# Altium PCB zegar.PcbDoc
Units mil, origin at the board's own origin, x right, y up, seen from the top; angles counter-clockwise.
Board outline 6000 x 4000 mil, 2 copper layers (Top Layer, Bottom Layer); 33 components, 30 nets, 135 pads, 16 vias.
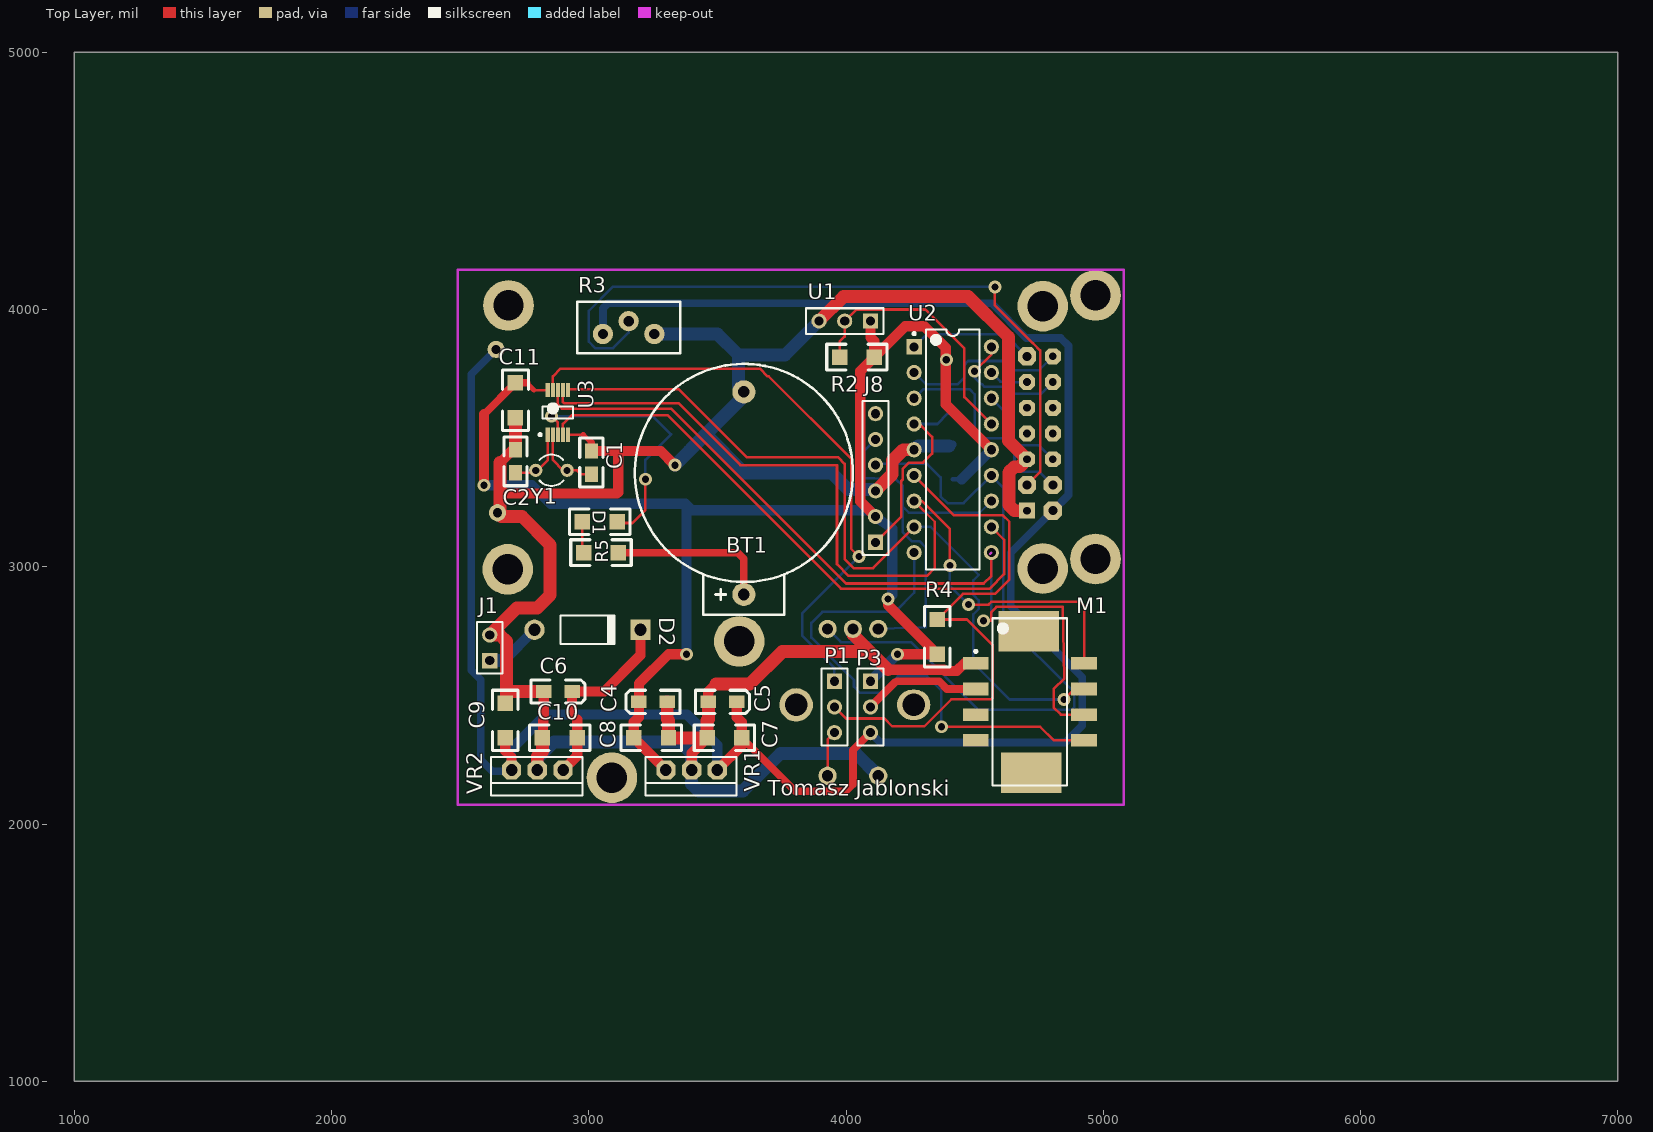
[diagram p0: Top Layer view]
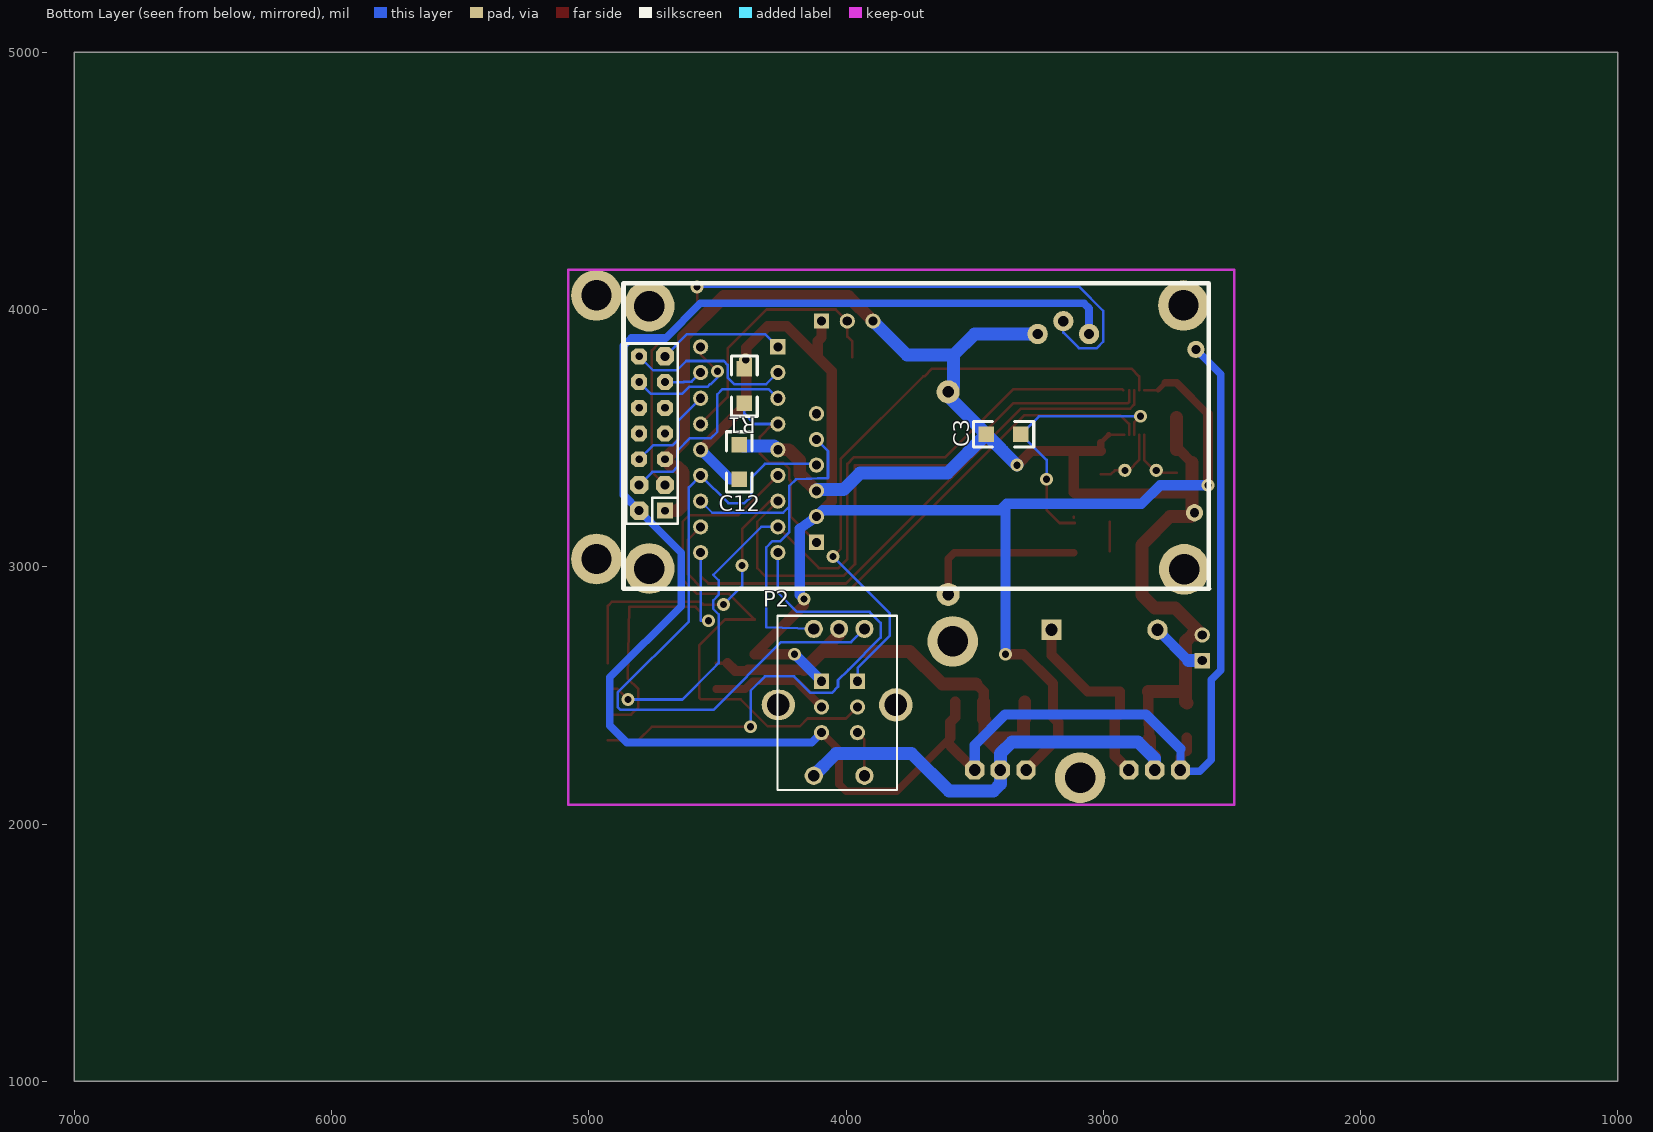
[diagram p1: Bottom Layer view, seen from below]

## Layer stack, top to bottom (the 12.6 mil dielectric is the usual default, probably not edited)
Top Layer: signal copper 1.4
Dielectric: dielectric 12.6, FR-4, Dk 4.8
Bottom Layer: signal copper 1.4

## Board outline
1000,1000 7000,1000 7000,5000 1000,5000

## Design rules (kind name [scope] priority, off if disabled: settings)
Clearance [All] p1: gap=10
PolygonConnect [All] p1: connectstyle=Relief reliefconductorwidth=10 reliefentries=4 polygonreliefangle="90 Angle"
RoomDefinition zegar [InComponentClass('zegar')] p1: confinementstyle=ConfineIn formatcopy=TRUE lockcomponents=FALSE outline 0,0 2000,0 2000,1000 0,1000
RoutingVias [All] p1: holewidth=28 width=50 viastyle="Through Hole" minholewidth=28 minwidth=50 maxholewidth=28 maxwidth=50
SMDNeckDown SMD+3,3 [InNet('+3,3V')] p1: percent=50.000
SMDNeckDown SMD_gnd [InNet('GND')] p2: percent=50.000
SilkscreenOverComponentPads [All] p1: minsilkscreentomaskgap=10
SolderMaskExpansion [All] p1: expansion=4
Width +5V [InNet('+5V')] p1: maxlimit=30 minlimit=10 preferedwidth=30
Width +3,3V [InNet('+3,3V')] p2: maxlimit=40 minlimit=10 preferedwidth=40
Width GND [InNet('GND')] p3: maxlimit=50 minlimit=40 preferedwidth=50
27 further rules are at their usual default settings.

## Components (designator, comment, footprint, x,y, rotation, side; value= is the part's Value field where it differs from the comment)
BT1 "Battery" BAT -3405,-4155 r270 top
C1 "22p" 0805 3010,3450 r270 top
C2 "22p" 0805 2715,3455 r270 top
C3 "100n" 1206 3455,3515 r180 bottom
C4 "Cap Pol2" 3216 3195,2475 r180 top
C5 "" 3216 3575,2475 r0 top
C6 "" 3216 2935,2515 r0 top
C7 "Cap" 1206 3595,2335 r180 top
C8 "Cap" 1206 3175,2335 r0 top
C9 "Cap" 1206 2675,2335 r90 top
C10 "Cap" 1206 2955,2335 r180 top
C11 "100n" 1206 2715,3715 r270 top
C12 "100n" 1206 4415,3475 r270 bottom
D1 "Diode" 1206 2975,3175 r0 top
D2 "1N4007" DIO10.46-5.3x2.8 2995,2755 r0 top
J1 "PWR" HDR1X2 2615,2635 r90 top
J8 "ICSP" HDR1X6 4115,3095 r90 top
M1 "TR52B" TR52B 4715,2475 r0 top
P1 "imp_sel" HDR1X3 3955,2555 r270 top
P2 "imp" IMP_PIHER 4015,2475 r0 bottom
P3 "TR52_PW" HDR1X3 4095,2555 r270 top
R1 "1k" 1206 4395,3635 r90 bottom
R2 "1k" 1206 3975,3815 r0 top
R3 "" PR 3155,3955 r180 top
R4 "1k" 1206 4355,2795 r270 top
R5 "1K" 1206 3115,3055 r180 top
U1 "DS18B20" HDR1X3 4095,3955 r180 top
U2 "PIC16F88" DIP-18 4415,3455 r0 top
U3 "MCP79512" MCP79512 2880,3600 r90 top
VR1 "Volt Reg" 78XXST 3475,2195 r180 top
VR2 "Volt Reg" 78XXST 2875,2195 r180 top
Y1 "XTAL" BCY-W2/D3.1 2855,3375 r270 top
? "LCD" lcd1x6 3735,3695 r180 bottom

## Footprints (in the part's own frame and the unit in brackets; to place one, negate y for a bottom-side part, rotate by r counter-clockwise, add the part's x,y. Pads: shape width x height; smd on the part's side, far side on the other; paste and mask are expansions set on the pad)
78XXST [mil]
  oct 75x75 hole 45: 1(-25,-15) 2(75,-15) 3(175,-15)
  silkscreen extent -100,-65 255,85
0805 [mil]
  rect 60x50 smd: 1(0,0) 2(90,0)
  silkscreen extent -50,-45 140,45
1206 [mil]
  rect 60x60 smd: 1(0,0) 2(135,0)
  silkscreen extent -50,-50 185,50
3216 [mil]
  rect 60x50 smd: 1(0,0) 2(-110,0)
  silkscreen extent -160,-45 50,45
BAT [mil]
  round 90 hole 45: 1(-7047.24,7007.87) 2(-7834.65,7007.87)
  silkscreen extent -7944,6584 -6969,7432
BCY-W2/D3.1 [mm] "Crystal, Thru-Hole; 2 Leads; Body 3.1 x 8.2 mm (Dia.xH)"
  round 1.3 hole 0.7: 1(0,1.55) 2(0,-1.55)
  silkscreen extent -1.55,-1.19 1.55,1.17
DIO10.46-5.3x2.8 [mm] "Diode, Axial; Body 5.2 x 2.7 mm (LxDia. max), Lead Dia. 0.86 mm (max)"
  round 2 hole 1.2: 1(-5.23,0)
  rect 2x2 hole 1.2: 2(5.23,0)
  silkscreen extent -2.65,-1.4 2.75,1.4
DIP-18 [mm] "DIP; 18 Leads; Row Spacing 7.62 mm; Pitch 2.54 mm"
  rect 1.5x1.5 hole 0.9: 1(-3.81,10.16)
  round 1.5 hole 0.9: 2(-3.81,7.62) 3(-3.81,5.08) 4(-3.81,2.54) 5(-3.81,0) 6(-3.81,-2.54) 7(-3.81,-5.08) 8(-3.81,-7.62) 9(-3.81,-10.16) 10(3.81,-10.16) 11(3.81,-7.62) 12(3.81,-5.08) 13(3.81,-2.54) 14(3.81,0) 15(3.81,2.54) 16(3.81,5.08) 17(3.81,7.62) 18(3.81,10.16)
  silkscreen extent -3.93,-11.85 2.65,11.85, body extent -3.6,-11.8 3.6,11.8, height 5.08
HDR1X2 [mm] "Connector; Header; 2 Position"
  rect 1.5x1.5 hole 0.9: 1(0,0)
  round 1.5 hole 0.9: 2(2.54,0)
  silkscreen extent -1.27,-1.27 3.81,1.27
HDR1X3 [mm] "Connector; Header; 3 Position"
  rect 1.5x1.5 hole 0.9: 1(0,0)
  round 1.5 hole 0.9: 2(2.54,0) 3(5.08,0)
  silkscreen extent -1.27,-1.27 6.35,1.27
HDR1X6 [mm] "Connector; Header; 6 Position"
  rect 1.5x1.5 hole 0.9: 1(0,0)
  round 1.5 hole 0.9: 2(2.54,0) 3(5.08,0) 4(7.62,0) 5(10.16,0) 6(12.7,0)
  silkscreen extent -1.27,-1.27 13.97,1.27
IMP_PIHER [mm]
  round 1.8 hole 1.1: 1(-2.2,-7.2) 2(0.3,-7.2) 3(2.8,-7.2) 4(-2.2,7.3) 5(2.8,7.3)
  round 3.3 hole 2.2: 71(-5.3,0.3)
  oval 3.3x3 hole 2.2: 72(6.3,0.3)
  silkscreen extent -5.4,-8.5 6.4,8.7
lcd1x6 [mil]
  round 196.85 hole 118.11: 0(-1030,-702) 0(-1030,318) 0(1047,321) 0(1050,-705)
  rect 62x62 hole 30: 1(-969,-477)
  oct 70.87x70.87 hole 35.43: 2(-1069,-477) 3(-969,-377) 4(-1069,-377) 13(-969,123)
  oct 62x62 hole 30: 5(-969,-277) 6(-1069,-277) 7(-969,-177) 8(-1069,-177) 9(-969,-77) 10(-1069,-77) 11(-969,23) 12(-1069,23) 14(-1069,123)
  round 66.93 hole 35.43: 15(1095,150) 16(1090,-485)
  silkscreen extent -1130,-781 1146,407
MCP79512 [mm] "SSOP, 10-Leads, Body 3.0x3.0mm (max), Pitch 0.50mm, IPC Medium Density"
  rect 1.4x0.4 smd: 1(-2.2,1) 2(-2.2,0.5) 3(-2.2,0) 4(-2.2,-0.5) 5(-2.2,-1) 6(2.2,-1) 7(2.2,-0.5) 8(2.2,0) 9(2.2,0.5) 10(2.2,1)
  silkscreen extent -2.32,-1.5 0.7,1.87, body extent -1.5,-1.5 1.5,1.5, height 2.65
PR [mil]
  round 79 hole 40: 1(-100,50) 2(100,50) W(0,0)
  silkscreen extent -200,-75 200,125
TR52B [mm]
  rect 6x4 smd: 0(-0.127,6.985) 0(0.127,-6.985)
  rect 2.55x1.25 smd: 1(-5.35,-3.81) 2(-5.35,-1.27) 3(-5.35,1.27) 4(-5.35,3.81) 5(5.35,-3.81) 6(5.35,-1.27) 7(5.35,1.27) 8(5.35,3.81)
  silkscreen extent -5.47,-8.25 3.68,8.25

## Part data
BT1: "Multicell Battery"
C1 C2 C3 C11 C12: library part Cap, "Capacitor"
C4: "Polarized Capacitor (Axial)"
C5 C6: library part "Cap Pol2", "Polarized Capacitor (Axial)"
C7 C8 C9 C10: "Capacitor"
D1: "Default Diode"
D2: library part "Diode 1N4007", "1 Amp General Purpose Rectifier"
J1: library part "Header 2", "Header, 2-Pin"
J8: library part "Header 6", "Header, 6-Pin"
M1: library part "Header 4X2A", "Header, 4-Pin, Dual row"
P1 P3 U1: library part "Header 3", "Header, 3-Pin"
P2: library part "Header 5", "Header, 5-Pin"
R1 R2 R4 R5: library part res2, "Resistor"
R3: library part RPot, "Potentiometer"
U2: library part PIC16F62X
VR1 VR2: "Voltage Regulator"
Y1: "Crystal Oscillator"

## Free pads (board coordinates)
  round 196.85 hole 118.11: 3(3090,2180) 3(3585,2710) 3(4970,3030) 3(4970,4055)

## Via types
v1: diameter 50, hole 28, Top Layer to Bottom Layer, 16 vias

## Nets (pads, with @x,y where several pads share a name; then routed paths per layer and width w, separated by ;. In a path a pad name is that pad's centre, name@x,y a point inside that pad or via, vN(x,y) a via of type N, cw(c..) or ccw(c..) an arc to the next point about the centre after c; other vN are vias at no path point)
1-WIRE: R2.1 U1.2 U2.15 | length 1031.6
  Top Layer w10: R2.1 3975,3875 3995,3895 U1.2 4040,4000 4308.31,4000 4460,3848.31 4460,3660 U2.15
+3,3V: C4.1 C8.1 C11.1 C12.2 J8.2 P3.1 R1.2 R2.2 R4.2 U1.1 U2.14 U3.10 VR1.3 | length 6162.2
  Top Layer w10: 2786.61,3686.61 U3.10
  Top Layer w20: 2758.23,3715 2786.61,3686.61
  Top Layer w30: 2593,3593 C11.1 2758.23,3715
  Top Layer w40: v1(2593,3317) 2593,3593 ; VR1.3 3257,2253 C8.1 3175,2395 3195,2415 3195,2545 3310,2660 v1(3380,2660) ; U1.1 4095,3892 4110,3877 R2.2 ; J8.2 4055,3255 4055,3760 R2.2 ; v1(4163,2875) 4163,2852 R4.2 v1(4200,2660) ; U2.14 4388,3632 4388,3851 4304,3935 4230,3935 R2.2
  Bottom Layer w18: C12.2 4450,3340
  Bottom Layer w40: v1(2593,3317) 2779,3317 2851.2,3244.8 3375.2,3244.8 3400,3220 4090,3220 J8.2 4179.31,3148.69 4179.31,2891.31 v1(4163,2875) ; v1(3380,2660) 3380,3175 3380,3235 ; P3.1 v1(4200,2660) ; 4450,3340 U2.14
  other v1: 4390,3805
+5V: ?.2 ?.15 C5.1 C7.1 C9.1 P3.3 R3.2 VR1.1 VR2.3 | length 8616.3
  Top Layer w30: 2675,2285 2700,2260 ; C7.1@3595,2305 C7.1 3803,2127 3999,2127 4027,2155 4027,2287 P3.3
  Top Layer w40: 2675,2285 C9.1 ; VR2.3 2700,2260 ; VR1.1 C7.1@3595,2305 ; C5.1 3575,2415 3595,2395 C7.1
  Bottom Layer w30: ?.15 2543,3748 2543,2597.94 2580,2560.94 2580,2250 2625,2205 2695,2205 VR2.3 2700,2292.07 ; R3.2 3055,4004 3075,4024 4566,4024 4701,3889 4835,3889 4865,3859 4865,3279 ?.2 4641,3055 4641,2847 4918,2570 4918,2383 4852,2317 4133,2317 P3.3
  Bottom Layer w40: 2700,2292.07 2833.93,2426 3381.22,2426 3500,2307.22 VR1.1
ALM: P1.1 U3.9 | length 2391.4
  Top Layer w10: 2860,3740 2860.31,3740.31 ; U3.9 2860.31,3740.31 ; v1(4050,3040) 4020,3070 4020,3420 3699.69,3740.31 3694.69,3740.31 3665,3770 2890,3770 2860.31,3740.31
  Bottom Layer w10: P1.1 3955,2606.72 3830,2731.72 3830,2820 v1(4050,3040)
GND: ?.1 ?.5 ?.16 BT1.2 C1.1 C2.1 C3.1 C4.2 C5.2 C6.2 C7.2 C8.2 C9.2 C10.2 C11.2 C12.1 J1.2 J8.3 M1.4 P2.2 P2.5 R3.1 U1.3 U2.5 U3.5 VR1.2 VR2.2 | length 10769.3
  Top Layer w10: U3.5 2978.39,3513.39
  Top Layer w14.76: M1.4@4460.81,2625 M1.4
  Top Layer w20: 2978.39,3513.39 3010,3481.77
  Top Layer w25: C2.1@2705,3455 C2.1
  Top Layer w30: C1.1 3010,3481.77
  Top Layer w40: 2655,3285 3110,3285 3115,3290 3115,3450 ; 2655,3405 C2.1@2705,3455 ; C10.2 2825,2430 C6.2 ; C1.1 3115,3450 ; v1(3335,3395) 3280,3450 3115,3450 ; VR1.2 3400,2275 C7.2 ; C5.2 3465,2515 3494,2544 ; 4165,2600 4380.64,2600 4385.64,2595 4430.81,2595 M1.4@4460.81,2625
  Top Layer w50: ?.16@2655,3215 2655,3285 2655,3405 ; ?.16@2660,3195 2740,3195 2850,3085 2850,2890 2800,2840 2720,2840 J1.2 2655,2735 2679.53,2710.47 2679.53,2515 ; C9.2 2679.53,2474.53 2679.53,2515 ; C2.1 C11.2 ; VR2.2 2800,2262 2820,2282 C10.2 ; C6.2 2679.53,2515 ; C4.2 3305,2407 3310,2402 C8.2 C7.2 3460,2402 3465,2407 C5.2 ; 3494,2544 3626,2544 3752,2670 4091.2,2670 ; U1.3 3990,4050 4475,4050 4632,3893 4632,3490 ?.5 4675,3389 4655,3389 4633,3367 4633,3240 4655,3218 ?.1 ; P2.2 4026.81,2736.19 4163,2600 ; J8.3 4180,3360 4180,3412.5 4222.5,3455 U2.5
  Bottom Layer w30: 4330,3475 C12.1
  Bottom Layer w50: VR2.2 2800,2254.5 2864.5,2319 3355,2319 3400,2274 VR1.2 3400,2155 3427,2128 3599,2128 3745,2274 4038.83,2274 P2.5 ; R3.1 3499.88,3905 3582.13,3822.76 ; v1(3335,3395) C3.1 ; 3390,3450 C3.1 ; U1.3 3762.76,3822.76 3582.13,3822.76 ; J8.3 4110.2,3299.8 4010.2,3299.8 3945,3365 3605,3365 C3.1 ; U2.5 4280,3470 C12.1@4400,3470 ; C3.1 3602.87,3662.87 BT1.2 3582.13,3700.39 3582.13,3822.76
INT: P1.2 R4.1 U2.6 | length 2166.2
  Top Layer w10: P1.2 4000,2410 4149,2410 4179,2380 4305,2380 4410,2485 4565,2485 4570,2490 4570,2695 4470,2795 R4.1 4454.55,2894.55 4578.55,2894.55 4635,2951 4635,3175 4610,3200 4420,3200 U2.6
LCD_D0: ?.11 U2.17 | length 154.3
  Bottom Layer w10: U2.17 4600.47,3719.53 4629.53,3719.53 4631.06,3718 ?.11
LCD_D1: ?.12 U2.18 | length 495.8
  Top Layer w10: v1(4500,3760) 4565,3825 U2.18
  Bottom Layer w10: v1(4500,3760) 4500,3735.53 4525.53,3710 4528.76,3710 4539.23,3699.53 4610,3699.53 4637.53,3672 4758,3672 ?.12
LCD_D2: ?.13 U2.1 | length 494.9
  Bottom Layer w10: U2.1 4314,3904 4618,3904 ?.13
LCD_D3: ?.14 U2.2 | length 661.5
  Bottom Layer w10: U2.2 4310,3710 4435,3710 4460,3735 4460,3785 4475,3800 4621,3800 4657,3764 4750,3764 ?.14
LCD_E: ?.6 U2.16 | length 379.9
  Bottom Layer w10: U2.16 4652,3568 4652,3495 4675,3472 4750,3472 ?.6
LCD_RS: ?.4 U2.3 | length 829.8
  Bottom Layer w10: U2.3 4300,3690 4480,3690 4480,3690.47 4500.47,3670 4500.47,3524.53 4525,3500 4606,3500 4655,3451 4655,3389 4675,3369 4753,3369 ?.4
Net_3: ?.3 | length 2837.6
  Top Layer w10: v1(4579,4088) 4579,4016 4726.57,3868.43 4727.93,3868.43 4755,3841.36 4755,3369 ?.3
  Bottom Layer w10: 3155,3955 3155,3910 3095,3850 3025,3850 3000,3875 3000,3995 3093,4088 v1(4579,4088)
NetBT1_1: BT1.1 R5.1 | length 636.7
  Top Layer w30: R5.1 3579.11,3055 3602.87,3031.24 BT1.1
NetC1_2: C1.2 U3.2 Y1.1 | length 270.7
  Top Layer w10: U3.2 2860.31,3415.31 2900.63,3375 Y1.1 2955,3375 2970,3360 C1.2
NetC2_2: C2.2 U3.1 Y1.2 | length 244.4
  Top Layer w10: C2.2 2783.98,3365 Y1.2 2800,3375 2840.63,3415.63 U3.1
NetC3_2: C3.2 D1.2 U3.3 | length 1053.1
  Top Layer w10: v1(2855,3585) 2880,3560 U3.3 ; D1.2@3110,3170 3170,3170 3220,3220 v1(3220,3340) v1@3220,3330
  Bottom Layer w10: v1(2855,3585) 3250,3585 C3.2 3220,3415 v1(3220,3340)
NetD1_1: D1.1 R5.2 | length 120
  Top Layer w10: R5.2@2975,3060 D1.1 ; 3115,3190 3115,3195
NetD2_1: D2.1 J1.1 | length 223.8
  Bottom Layer w40: 2669.09,2635 D2.1
  Bottom Layer w50: J1.1 2669.09,2635
NetM1_3: M1.3 P3.2 | length 451.1
  Top Layer w30: P3.2 4190,2550 ; 4200,2555 4362,2555 4392,2525 M1.3
NetP1_3: P1.3 P2.4 | length 178.4
  Top Layer w10: P2.4 3928.39,2328.39 P1.3
RB6: J8.5 P2.3 U2.12 | length 1573.3
  Bottom Layer w10: J8.5 4070,3450 4070,3345 4195,3340 4220,3315 ; P2.3 4310,2764.47 4310,3075 4285,3100 4255,3100 4220,3135 4220,3235 ; U2.12 4520,3210 4245,3210 4220,3235 ; 4220,3235 4220,3315 ; 4220,3235 4220,3315
RB7: J8.4 P2.1 U2.13 | length 2731.2
  Bottom Layer w10: P2.1 3979.85,2707 4252,2707 4515,2444 4877,2444 4888,2455 4888,2511 4611,2788 4611,3309 U2.13 4457,3247 4395,3247 4368,3274 4368,3347 4315,3400 4120,3400 J8.4
RST: J8.1 R1.1 U2.4 | length 810.6
  Top Layer w10: J8.1 4215,3195 4215,3333.43 4220,3338.43 4220,3380 4245,3405 4300,3405 4335,3440 4335,3505 4285,3555 U2.4
  Bottom Layer w10: U2.4 4355,3555 4395,3595 R1.1
SPI_CSRD: M1.5 U2.9 | length 2037.6
  Top Layer w10: v1(4371,2378) 4755,2378 4808,2325 M1.5
  Bottom Layer w10: U2.9 4265,2899 4191,2825 3907.95,2825 3865,2782.05 3865,2725 3990.47,2599.53 3990.74,2599.53 4031,2559.27 4031,2534 4055,2510 4138,2510 4202,2574 4315,2574 4371,2518 v1(4371,2378)
SPI_CST: U2.11 U3.4 | length 2278.7
  Top Layer w10: U3.4 2899.69,3555 2934.37,3589.69 3305.31,3589.69 3980,2915 4558.99,2915 4615,2971.01 4615,3105 U2.11
SPI_SCK: M1.6 U2.10 U3.8 | length 3314.4
  Top Layer w10: U3.8 2880,3630 2895,3615 3320,3615 4000,2935 4535,2935 4565,2965 U2.10 ; v1(4535,2790) 4564,2790 4565,2791 4565,2824 4585,2844 4843,2844 4849,2566.18 4807.43,2524.61 4807.43,2452.57 4835,2425 M1.6
  Bottom Layer w10: v1(4535,2790) 4564,2790 4565,2791 U2.10
SPI_SDI: M1.8 U2.7 U3.7 | length 3494
  Top Layer w10: U3.7 2899.69,3640.31 2905,3635 3350,3635 3590,3395 3965,3395 3965,3010 4010,2965 4315,2965 4345,2995 4345,3175 U2.7 4295,3255 4404,3146 v1(4404,3005) ; v1(4476,2853) 4554,2853 4565,2864 4910,2864 4926,2848 4926,2625 M1.8
  Bottom Layer w10: v1(4404,3005) 4404,2925 v1(4476,2853)
SPI_SDO: M1.7 U2.8 U3.6 | length 3118.6
  Top Layer w10: U3.6@2922.56,3686.61 2925.95,3690 3350,3690 3615,3425 3970,3425 3995,3400 3995,3030 4030,2995 4105,2995 U2.8 ; v1(4848,2484) 4889,2525 M1.7
  Bottom Layer w10: U2.8 4329.53,3155 4516,2968.53 4495,2947.53 4495,2890.57 4516,2869.57 4516,2836.43 4495,2815.43 4495,2625 4516,2604 4636,2484 v1(4848,2484)
VCC: C6.1 C10.1 D2.2 VR2.1 | length 759.4
  Top Layer w10: 2935,2425 2955,2405
  Top Layer w40: VR2.1 2955,2265 C10.1 2955,2405 ; 2935,2425 C6.1 3060,2515 3200.91,2655.91 D2.2
pads on no net: ?.0 ?.7 ?.8 ?.9 ?.10 J8.6 M1.0 M1.1 M1.2 P2.71 P2.72 R3.W

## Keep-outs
Top Layer:
  lines w10: 4560,3050 4565,3055
Keep-Out Layer:
  lines w10: 2490,4155 2490,2075 5080,2075 5080,4150 ; 2495,4155 5080,4155

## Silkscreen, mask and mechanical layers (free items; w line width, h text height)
Top Overlay:
  text "Tomasz Jablonski" at 3695,2110 h60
